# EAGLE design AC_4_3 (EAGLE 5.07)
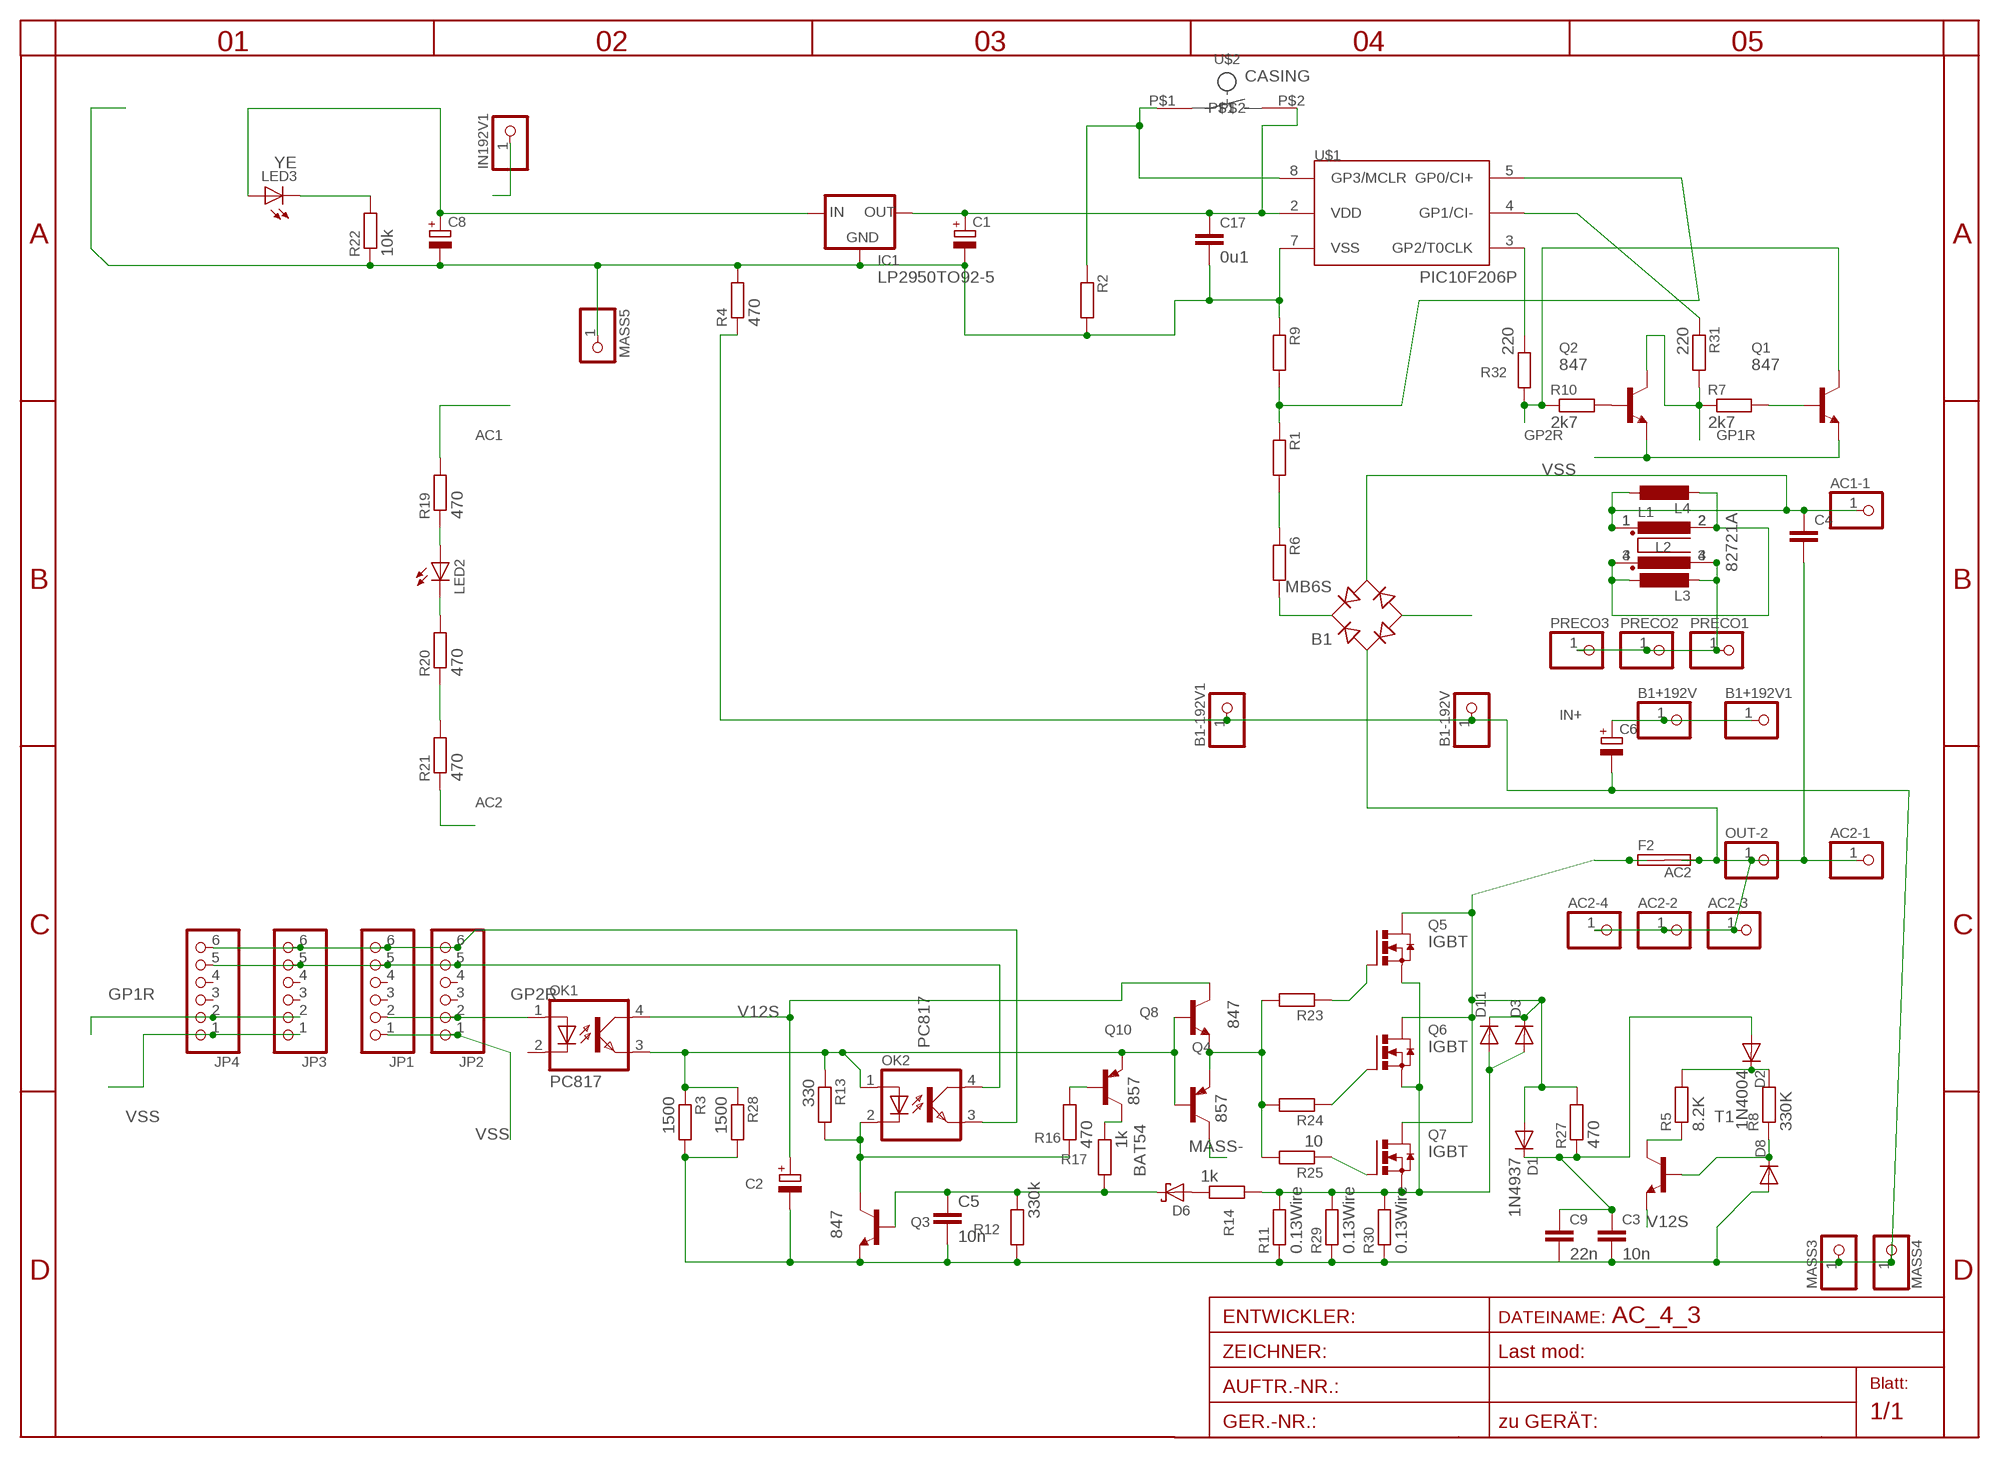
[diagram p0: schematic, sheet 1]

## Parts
AC1-1  PINHD-1X14.5MM  [1X4MM5]
AC2-1  PINHD-1X14.5MM  [1X4MM5]
AC2-2  PINHD-1X13MM2  [1X3MM2]
AC2-3  PINHD-1X13MM2  [1X3MM2]
AC2-4  PINHD-1X12MM3  [1X2MM3]
B1  MB6S  [SOIC-4]
B1+192V  PINHD-1X13MM2  [1X3MM2]
B1+192V1  PINHD-1X13MM2  [1X3MM2]
B1-192V  PINHD-1X13MM2  [1X3MM2]
B1-192V1  PINHD-1X13MM2  [1X3MM2]
C1  CPOL-EUE5-6  [E5-6]
C2  CPOL-EUE2.5-5  [E2,5-5]
C3  10n  C-EU025_050-050X075  [C025_050-050X075]
C4  C-EU225-108X268  [C225-108X268]
C5  10n  C-EUC0805  [C0805]
C6  CPOL-EUE10-20  [EB20D]
C8  CPOL-EUE5-5  [E5-5]
C9  22n  C-EU102-043X133  [C102-043X133]
C17  0u1  C-EUC1206  [C1206]
D1  1N4937  1N4004DO41-10  [DO41-10]
D2  1N4004  [DO41-20]
D3  DIODE-SMC  [SMC]
D6  BAT54  [SOT23]
D8  DIODE-MINIMELF  [MINIMELF]
D11  DIODE-SMC  [SMC]
F2  SHK20L7MM5  [7MM5]
IC1  LP2950TO92-5  [T092-5]
IN192V1  PINHD-1X13MM2  [1X3MM2]
JP1  PINHD-1X6  [1X06BOX]
JP2  PINHD-1X6  [1X06BOX]
JP3  PINHD-1X6  [1X06BOX]
JP4  PINHD-1X6  [1X06BOX]
L1  R1405VB1  [B1]
L2  82721A  [82721A]
L3  L-EU2200-15.24  [2200-15.24]
L4  L-EU2200-15.24  [2200-15.24]
LED2  LED3MM  [LED3MM]
LED3  YE  LEDCHIPLED_1206  [CHIPLED_1206]
MASS3  PINHD-1X13MM2  [1X3MM2]
MASS4  PINHD-1X13MM2  [1X3MM2]
MASS5  PINHD-1X11MM6  [1X1MM8]
OK1  PC817  [DIL04]
OK2  PC817  [DIL04]
OUT-2  PINHD-1X13MM2  [1X3MM2]
PRECO1  PINHD-1X12MM3  [1X2MM3]
PRECO2  PINHD-1X13MM2  [1X3MM2]
PRECO3  PINHD-1X12MM3  [1X2MM3]
Q1  847  BC847ALT1SMD  [SOT23]
Q2  847  BC847ALT1SMD  [SOT23]
Q3  847  BC846ALT1SMD  [SOT23]
Q4  857  BC857ALT1SMD  [SOT23-BEC]
Q5  IGBT  N-HEXFET_DPAK-  [TO252]
Q6  IGBT  N-HEXFET_DPAK-  [TO252]
Q7  IGBT  N-HEXFET_DPAK-  [TO252]
Q8  847  BC846ALT1SMD  [SOT23]
Q10  857  BC857ALT1SMD  [SOT23-BEC]
R1  R-EU_0207/40  [0207/40]
R2  R-EU_R0805  [R0805]
R3  1500  R-EU_R0805  [R0805]
R4  470  R-EU_0204/5  [0204/5]
R5  8.2K  R-EU_0204/5  [0204/5]
R6  R-EU_0207/50  [0207/50]
R7  2k7  R-EU_R0805  [R0805]
R8  330K  R-EU_0204/5  [0204/5]
R9  R-EU_R0805  [R0805]
R10  2k7  R-EU_R0805  [R0805]
R11  0.13Wire  R-EU_0204/5  [0204/5]
R12  330k  R-EU_R0805  [R0805]
R13  330  R-EU_R1206  [R1206]
R14  1k  R-EU_R0805  [R0805]
R16  470  R-EU_R0805  [R0805]
R17  1k  R-EU_R0805  [R0805]
R19  470  R-EU_0204/5  [0204/5]
R20  470  R-EU_0204/2V  [0204V]
R21  470  R-EU_0204/5  [0204/5]
R22  10k  R-EU_R1206  [R1206]
R23  R-EU_0207/15  [0207/15]
R24  R-EU_0207/10  [0207/10]
R25  10  R-EU_0207/15  [0207/15]
R27  470  R-EU_0207/10  [0207/10]
R28  1500  R-EU_R1206  [R1206]
R29  0.13Wire  R-EU_0204/5  [0204/5]
R30  0.13Wire  R-EU_0204/5  [0204/5]
R31  220  R-EU_R1206  [R1206]
R32  220  R-EU_R1206  [R1206]
T1  -NPN-TO92-EBC  [TO92-EBC]
U$1  PIC10F206P  [DIL8]
U$2  CASING  [CASING]

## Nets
AC1: AC1-1.1 B1.~2(AC2) C4.1 L1.1 L2.1 L4.1 R19.2
AC2: AC2-1.1 AC2-2.1 AC2-3.1 AC2-4.1 B1.~1(AC1) C4.2 F2.2A F2.2B OUT-2.1 R21.1
BATT+: C8.+ IC1.3(IN) LED3.A
D1: D1.A D3.C D11.C F2.1A F2.1B Q5.3(D) Q6.3(D) Q7.3(D) R27.2
GP1R: JP3.2 JP4.2 Q2.3(C) R7.1 R31.2
GP2R: JP1.2 JP2.2 OK1.1(A) Q1.3(C) R10.1 R32.2
GP3: JP1.6 JP2.6 JP3.6 JP4.6 OK2.3(EMIT) R2.1 U$1.8(GP3/MCLR) U$2.P$1
IN+: B1+192V1.1 B1+192V.1 C6.+ IN192V1.1
INN: L1.2 L1.3 L2.2 L2.4 L3.1 L4.2
MASS-: B1-192V1.1 B1-192V.1 B1.- C2.- C3.3 C5.2 C6.- C9.2 D8.A MASS3.1 MASS4.1 Q3.2(E) Q4.C R3.2 R4.1 R11.1 R12.2 R28.2 R29.1 R30.1
N$1: R1.1 R9.2 U$1.5(GP0/CI+)
N$2: C3.1 C9.1 D1.C D2.A R27.1
N$3: R1.2 R6.1
N$4: Q2.1(B) R10.2
N$6: LED2.A R19.1
N$7: Q1.1(B) R7.2
N$9: LED2.K(C) R20.2
N$11: C5.1 D6.3(C) Q3.1(B) R12.1 R17.2
N$12: OK2.2(C) Q3.3(C) R13.2 R16.1
N$13: R20.1 R21.2
N$14: D6.1(A) R14.1
N$15: LED3.C R22.2
N$16: Q10.B R16.2
N$17: Q10.C R17.1
N$20: D2.C R5.2 R8.2
N$25: Q7.1(G) R25.1
N$26: Q6.1(G) R24.1
N$27: Q5.1(G) R23.1
N$33: B1.+ R6.2
N$34: R5.1 T1.C
N$36: D8.C R8.1 T1.B
N$37: Q4.E Q8.2(E) R23.2 R24.2 R25.2
N$39: R31.1 U$1.4(GP1/CI-)
N$43: R32.1 U$1.3(GP2/T0CLK)
PP1: OK1.3(EMIT) OK2.1(A) Q4.B Q8.1(B) Q10.E R3.1 R13.1 R28.1
PRECOIL: L1.4 L2.3 L3.2 PRECO1.1 PRECO2.1 PRECO3.1
SRC1: D3.A D11.A Q5.2(S) Q6.2(S) Q7.2(S) R11.2 R14.2 R29.2 R30.2
V12S: C2.+ OK1.4(COL) Q8.3(C) T1.E
VDD: C1.+ C17.1 IC1.1(OUT) JP1.5 JP2.5 JP3.5 JP4.5 OK2.4(COL) U$1.2(VDD) U$2.P$2
VSS: C1.- C8.- C17.2 IC1.2(GND) JP1.1 JP2.1 JP3.1 JP4.1 MASS5.1 Q1.2(E) Q2.2(E) R2.2 R4.2 R9.1 R22.1 U$1.7(VSS)
Unconnected: JP1.3 JP1.4 JP2.3 JP2.4 JP3.3 JP3.4 JP4.3 JP4.4 OK1.2(C)

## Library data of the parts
AC1-1 AC2-1-AC2-4 B1+192V B1+192V1 B1-192V B1-192V1 IN192V1 MASS3-MASS5 OUT-2 PRECO1-PRECO3 = pinhead:PINHD-1X1: PIN HEADER
B1 = rectifier:MB*S: Bridge Rectifier Source: http://www.fairchildsemi.com/ds/MB/MB6S.pdf
C1 C2 C8 = rcl-2:CPOL-EU: POLARIZED CAPACITOR, European symbol
C3 C9 C17 = rcl-2:C-EU: CAPACITOR, European symbol
C4 C5 = rcl:C-EU: CAPACITOR, European symbol
C6 = rcl:CPOL-EU: POLARIZED CAPACITOR, European symbol
D1 D2 = diode:1N4004: DIODE
D3 D8 D11 = diode:DIODE-: DIODE
D6 = diode:BAT54: Schottky Diodes
F2 = fuse:SHK20L: FUSE HOLDER 5 x 20 mm, SH contact, SHH1 Schukat, E1073 Buerklin
IC1 = v-reg:LP2950?*: Source: http://cache.national.com/ds/LP/LP2950.pdf
JP1-JP4 = pinhead:PINHD-1X6: PIN HEADER
L1 = inductor-nkl:R1405V: Übertrager (verlustarm) bis typ. 400kHz Power transformer (low loss) up to typ. 400kHz
L2 = inductors:82721A: FILTER
L3 L4 = rcl:L-EU: INDUCTOR, European symbol
LED2 LED3 = led:LED: LED
OK1 OK2 = optocoupler:PC817: SHARP OPTO COUPLER
Q1 Q2 = transistor-npn:BC847*: NPN Transistor
Q3 Q8 = transistor-npn:BC846*: NPN Transistor
Q4 Q10 = transistor-pnp:BC857*: PNP Transistror
Q5-Q7 = transistor-power:N-HEXFET_?-*: HEXFET® Power MOSFET
R1-R14 R16 R17 R19-R25 R27-R32 = rcl-2:R-EU_: RESISTOR, European symbol
T1 = transistor-neu-to92:*-NPN-: NPN Transistror
U$1 = microchip-5:PIC10F2*: uPC nW 0,25/0,5k Program Flash memory Comparator
U$2 = button:CASING

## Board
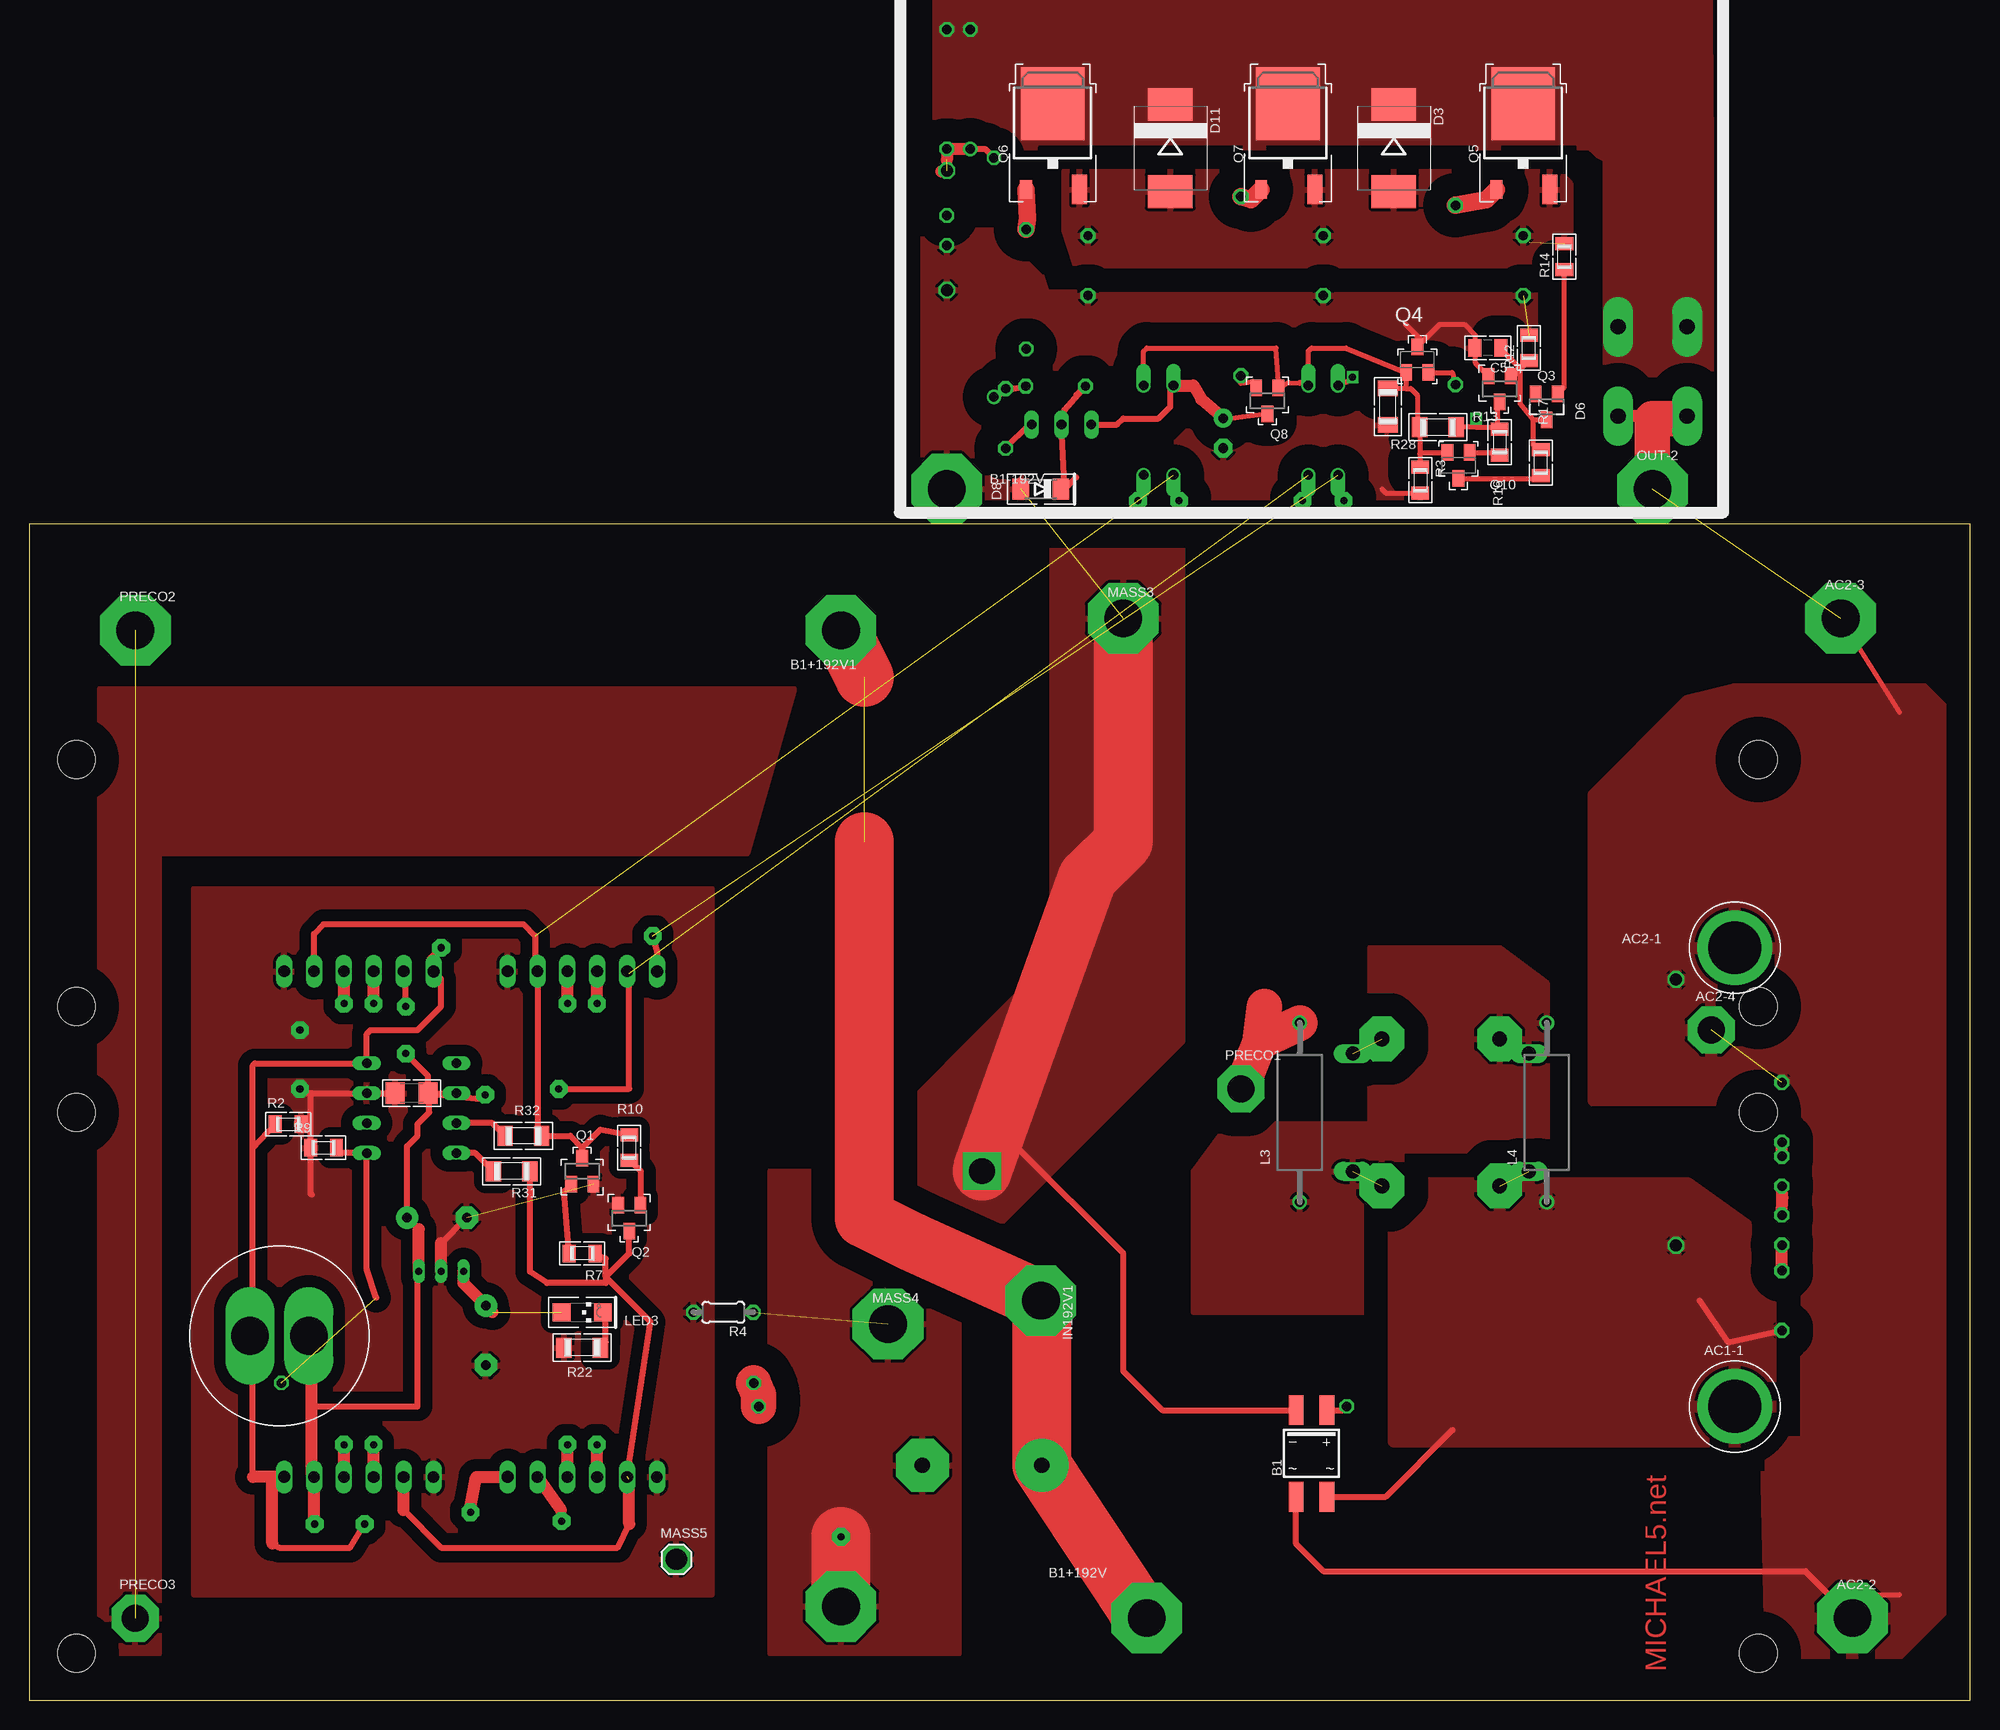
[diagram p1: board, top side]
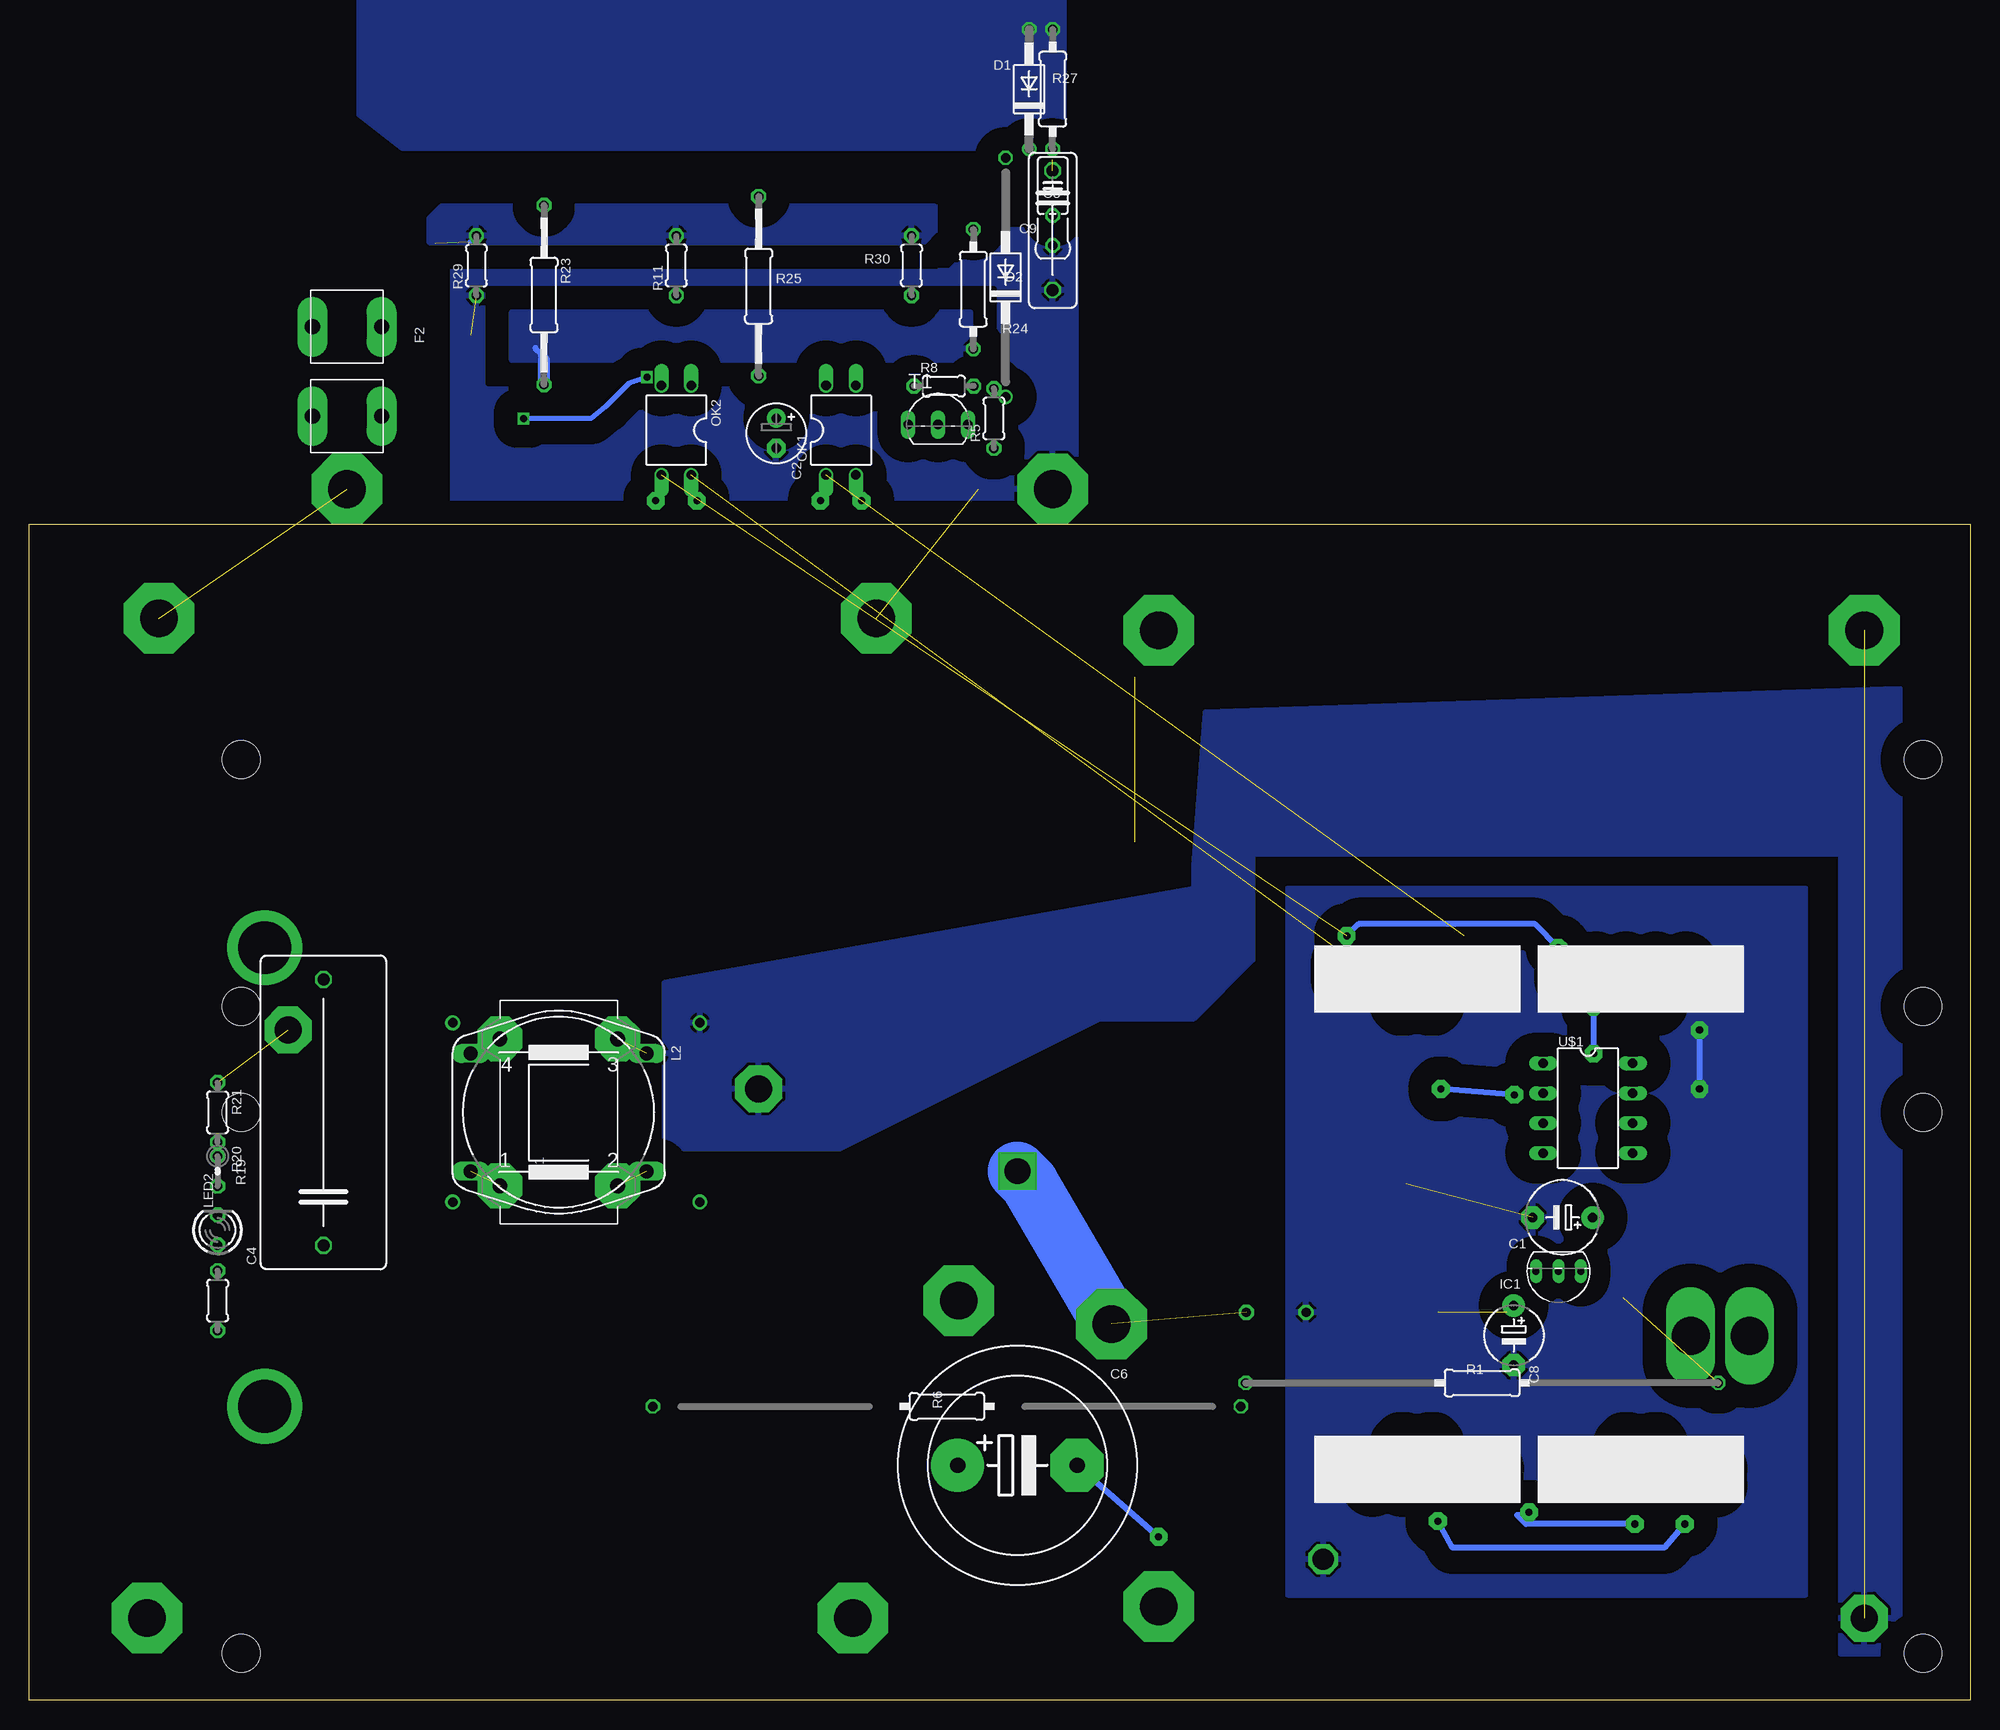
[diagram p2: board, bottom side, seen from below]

Size 165 x 100 mm. Coordinates in mm from the lower left corner, seen from the top.
Outline: 0,0 165,0 165,100 0,100 0,0
Copper layers (1*16): Top 0.035mm / dielectric 1.5mm / Bottom 0.035mm
Design rules "default *": minimum track width 12mil, minimum drill 24mil, track to track 8mil, track to pad 8mil, pad to pad 8mil, via to via 8mil, smd to smd 8mil, copper to edge 40mil, drill to drill 8mil, minimum pad ring 8mil, minimum via ring 8mil, stop-mask expansion 4mil, vias tented up to drill 0mil, thermal gap 10mil
Holes 3.2 mm at 4,80 4,4 4,59 4,50 147,80 147,4 147,59 147,50

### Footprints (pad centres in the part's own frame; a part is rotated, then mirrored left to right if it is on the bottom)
1X4MM5 = drill 4.5 pad 6.35 round: 1 0,0
1X3MM2 = drill 3.2 pad 6 octagon: 1 0,0
1X2MM3 = drill 2.3 pad 4 octagon: 1 0,0
SOIC-4 = smd 1.27 x 2.54: + 1.3,3.685; - -1.3,3.685; ~1 -1.3,-3.685; ~2 1.3,-3.685
E5-6 = drill 0.813 pad 1.905 round: + -2.54,0 | drill 0.813 pad 1.905 octagon: - 2.54,0
E2,5-5 = drill 0.813 pad 1.6 round: + -1.27,0 | drill 0.813 pad 1.6 octagon: - 1.27,0
C025_050-050X075 = drill 0.813 octagon: 1 -3.81,0; 2 0,0; 3 2.54,0
C225-108X268 = drill 1.016 octagon: 1 -11.303,0; 2 11.303,0
C0805 = smd 1.1 x 1.5: 1 -1.1,0; 2 1.1,0
EB20D = drill 1.3 pad 4.5 round: + -5.08,0 | drill 1.3 pad 4.5 octagon: - 5.08,0
E5-5 = drill 0.813 pad 1.905 round: + -2.54,0 | drill 0.813 pad 1.905 octagon: - 2.54,0
C102-043X133 = drill 1.016 octagon: 1 -5.08,0; 2 5.08,0
C1206 = smd 1.6 x 1.8: 1 -1.4,0; 2 1.4,0
DO41-10 = drill 0.8 octagon: A 5.08,0 | drill 0.8 round: C -5.08,0
DO41-20 = drill 0.8 octagon: A 10.16,0 | drill 0.8 round: C -10.16,0
SMC = smd 2.8 x 3.8: A 3.7,0; C -3.7,0
SOT23 = smd 1 x 1.4: 1 -0.95,-1.1; 2 0.95,-1.1; 3 0,1.1
MINIMELF = smd 1.4 x 1.8: A 1.7,0; C -1.7,0
7MM5 = drill 1.3 pad 2.54 long: 1A -3.8,2.94; 1B -3.8,-2.94; 2A 3.8,2.94; 2B 3.8,-2.94
T092-5 = drill 0.6 pad 0.813 long: 1 -1.905,0; 2 0,0; 3 1.905,0
1X06BOX = drill 1 long: 1 -6.35,0; 2 -3.81,0; 3 -1.27,0; 4 1.27,0; 5 3.81,0 | drill 1.016 long: 6 6.35,0
B1 = drill 1.27 pad 3.81 octagon: 1 -6.25,5; 2 -6.25,-5; 3 6.25,5; 4 6.25,-5
82721A = drill 1.194 long: 1 7.493,5.004; 2 -7.493,5.004; 3 -7.493,-5.004; 4 7.493,-5.004
2200-15.24 = drill 0.8 pad 1.27 round: 1 -7.62,0; 2 7.62,0
LED3MM = drill 0.8 pad 1.27 octagon: A -1.27,0; K 1.27,0
CHIPLED_1206 = smd 1.5 x 1.5: A 0,-1.75; C 0,1.75
1X1MM8 = drill 1.8 pad 2.54 octagon: 1 0,0
DIL04 = drill 0.813 offset: 1 -1.27,-3.81; 2 1.27,-3.81; 3 1.27,3.81; 4 -1.27,3.81
SOT23-BEC = smd 1 x 1.4: B -0.95,-1.1; C 0,1.1; E 0.95,-1.1
TO252 = smd 1 x 1.6: 1 -2.28,-3.53 | smd 1.27 x 2.54: 2 2.28,-3.53 | smd 5.4 x 6.2: 3 0,3.77
0207/40 = drill 0.813 octagon: 1 -20.08,0; 2 20.08,0
R0805 = smd 1.1 x 1.5: 1 -1.1,0; 2 1.1,0
0204/5 = drill 0.8 pad 1.27 octagon: 1 -2.54,0; 2 2.54,0
0207/50 = drill 0.813 octagon: 1 -25,0; 2 25,0
R1206 = smd 1.3 x 1.7: 1 -1.55,0; 2 1.55,0
0204V = drill 0.8 pad 1.27 octagon: 1 -1.27,0; 2 1.27,0
0207/15 = drill 0.8 pad 1.27 octagon: 1 -7.62,0; 2 7.62,0
0207/10 = drill 0.813 octagon: 1 -5.08,0; 2 5.08,0
TO92-EBC = drill 0.813 long: B 0,-1.27; C 2.54,-1.27; E -2.54,-1.27
DIL8 = drill 0.8 long: 1 -3.81,-3.81; 2 -1.27,-3.81; 3 1.27,-3.81; 4 3.81,-3.81; 5 3.81,3.81; 6 1.27,3.81; 7 -1.27,3.81; 8 -3.81,3.81
CASING = drill 3.2 pad 3.81 long: P$1 -2.5,0; P$2 2.5,0

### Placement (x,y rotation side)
AC1-1  145,25 0 top
AC2-1  145,64 0 top
AC2-2  155,7 0 top
AC2-3  154,92 0 top
AC2-4  143,57 0 top
B1  109,21 0 top
B1+192V  95,7 0 top
B1+192V1  69,91 180 top
B1-192V  78,103 0 top
B1-192V1  69,8 0 top
C1  34.65,41.07 180 bottom
C2  101.5,107.75 270 bottom  (outside the outline)
C3  not placed on the board
C4  140,50 90 bottom
C5  124,115 180 top  (outside the outline)
C6  81,20 0 bottom
C8  38.8,31.05 270 bottom
C9  78,125 270 bottom  (outside the outline)
C17  32.49,51.63 180 top
D1  80,137 90 bottom  (outside the outline)
D2  82,121 90 bottom  (outside the outline)
D3  not placed on the board
D6  129,110 180 top  (outside the outline)
D8  86,103 180 top
D11  not placed on the board
F2  138,113 270 bottom  (outside the outline)
IC1  35,36.5 180 bottom
IN192V1  86,34 270 top
JP1  47,62 180 bottom
JP2  28,62 180 bottom
JP3  28,19 0 bottom
JP4  47,19 0 bottom
L1  120,50 90 bottom
L2  120,50 180 bottom
L3  108,50 90 top
L4  129,50 90 top
LED2  149,40 90 bottom
LED3  47,33 270 top
MASS3  93,92 0 top
MASS4  73,32 0 top
MASS5  55,12 0 top
OK1  96,108 0 bottom  (outside the outline)
OK2  110,108 180 bottom  (outside the outline)
OUT-2  138,103 0 top
PRECO1  103,52 0 top
PRECO2  9,91 0 top
PRECO3  9,7 0 top
Q1  47,45 0 top
Q2  51,41 180 top
Q3  125,111.5 180 top  (outside the outline)
Q4  118,114 0 top  (outside the outline)
Q5  127,132 0 top  (outside the outline)
Q6  87,132 0 top  (outside the outline)
Q7  107,132 0 top  (outside the outline)
Q8  105.25,110.5 180 top  (outside the outline)
Q10  121.5,105 180 top  (outside the outline)
R1  41.5,27 180 bottom
R2  22,49 0 top
R3  118.25,103.75 270 top
R4  59,33 180 top
R5  83,109 90 bottom  (outside the outline)
R6  87,25 180 bottom
R7  47,38 180 top
R8  87.25,111.75 0 bottom  (outside the outline)
R9  25,47 0 top
R10  51,47 270 top
R11  not placed on the board
R12  127.5,115 90 top  (outside the outline)
R13  119.75,108.25 0 top  (outside the outline)
R14  130.5,122.75 90 top  (outside the outline)
R16  125,107 270 top  (outside the outline)
R17  128.5,105.25 90 top  (outside the outline)
R19  149,34 270 bottom
R20  149,45 270 bottom
R21  149,50 270 bottom
R22  47,30 0 top
R23  121.25,119.5 270 bottom  (outside the outline)
R24  84.75,120 270 bottom  (outside the outline)
R25  103,120.25 270 bottom  (outside the outline)
R27  78,137 90 bottom  (outside the outline)
R28  115.5,110 270 top  (outside the outline)
R29  127,122 90 bottom  (outside the outline)
R30  not placed on the board
R31  41,45 0 top
R32  42,48 0 top
T1  87.75,109.75 0 bottom  (outside the outline)
U$1  32.49,50.36 270 bottom
U$2  21.25,31 0 top

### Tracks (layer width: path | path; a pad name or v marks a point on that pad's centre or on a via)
AC1  (1 unrouted)
  Top 0.5: R19.2 144.46,30.46 142,34 | B1.~2 115.31,17.32 121,23
  pour Top (isolate 2): 116,44 141,44 148,39 148,22 116,22
AC2  (2 unrouted)
  Top 0.406: 159,84 AC2-3.1 | 159,9 155,9 AC2-2.1
  Top 0.5: B1.~1 107.7,13.3 110,11 151,11 AC2-2.1
  Top 1: F2.2A F2.2B 140.74,109 140,109
  Top 3: OUT-2.1 138,109 140,109
  pour Top (isolate 2, rank 2): 145,86 161,86 163,84 163,8 159,4 149,4 148,5 147,51 133,51 133,77 141,85
BATT+  (1 unrouted)
  Top 1: IC1.3 36.91,35.48 C8.+ 39.38,33
D1
  pour Top (isolate 2, rank 2, no thermals): 77,148 142.89,148 143,132 143,111 134,111 134,131 132,132 77,132
  pour Bottom (isolate 2, rank 2, no thermals): 77,148 137,148 137,134.82 133.35,132 77,132
GP1R  (1 unrouted)
  Top 0.5: R31.2 42.55,36.45 44,35.5 49,35.5 49,36 | 49,36 49,37.55 R7.1 | Q2.3 51,38 49,36 | 49,36 52.81,32.19 JP4.2 | 31.81,16.19 35,13 50,13 51,15
  Top 1: 51,15 51,18.81 | 31.81,16.19 JP3.2
GP2R  (1 unrouted)
  Top 0.5: R10.1 48.55,48.55 47,47 | 47,47 Q1.3 | 47,47 46,48 R32.2 43.19,48.36 JP1.2 43,62.19 43,65 42,66 25,66 24.19,65.19 JP2.2
GP3  (via drill 0.6 pad 1.5)  (1 unrouted)
  Top 0.5: 20.65,13.35 21.25,13 27.25,13 v28.5,15 | 19,19 19,27.5 U$2.P$1 19,32.5 19,47 | 19,47 R2.1 | 19,47 19,54 19.17,54.17 U$1.8 28.68,56.68 29,57 33,57 35,59 35,61.35 JP2.6 34,62.35 34,63 v35,64 | 20.65,18.65 21,19 | v37.5,16 37.5,16.5 | JP1.6 53.35,63.65 v53,65
  Top 1: 19,19 JP3.6 21,19 | 20.65,13.35 20.65,18.65 | 37.5,16.5 38,19 JP4.6
  Bottom 0.5: v28.5,15 37.75,15 38.5,15.75 v37.5,16 | v53,65 52,66 37,66 v35,64
IN+  (1 unrouted)
  Top 5: B1+192V.1 94.08,7.92 C6.+ 86.08,31.92 IN192V1.1 75,39 71,41 71,73 | 71,87 B1+192V1.1
INN  (1 unrouted)
  pour Top (isolate 2, rank 2): 114,64 125,64 129,61 129,46 114,46 114,33 99,33 99,45 102,49 114,49
MASS-  (via drill 0.6 pad 1.5, 2.2 pad 3)  (3 unrouted)
  Top 0.406: R3.2 115.35,102.65 115,103 | 118.3,115.7 117,117 | Q3.2 122.9,113.75 C5.2 122.9,116.1 122,117 119.9,117 Q4.C
  Top 0.5: B1.- 96.31,24.68 93,28 93,38 84,47
  Top 5: B1-192V1.1 v69,13.92 | MASS3.1 93,73 90,70 v81,45
  Bottom 0.5: v69,13.92 C6.-
  Bottom 5: MASS4.1 80,44 v81,45
  pour Top (isolate 2, rank 3): 76,125 82,125 86,121 129,121 129,102 76,102
  pour Bottom (isolate 2, rank 3): 76,125 82,125 86,122 129,122 129,102 76,102
  pour Top (isolate 2, rank 3): 87,99 98,98 98,56 79,37 79,4 63,4 63,45 69,45 87,63
N$1  (1 unrouted)
  Top 0.5: 29.5,34.25 28.68,36.68 U$1.5 26.55,46.55 R9.2
N$2  (2 unrouted)
  Top 0.5: D1.C 81.24,131.92 D2.A
  Top 1: D1.C R27.1 78,131 | C9.1 77.54,130
N$3
  Top 3: R6.1 62,26 R1.2
N$4
  Top 0.5: R10.2 51.55,45.45 52,45 52,42.15 Q2.1
N$5  (via drill 0.6 pad 1.5)
  Top 1: 48.25,19 v48.25,21.75
N$6
  Top 1.016: R19.1 LED2.A
N$7
  Top 0.5: R7.2 45.45,43.3 Q1.1
N$8  (via drill 0.6 pad 1.5)
  other vias: 45.75,21.75
N$9
  Top 1.016: R20.2 149.04,42.73 LED2.K
N$10  (via drill 0.6 pad 1.5)
  other vias: 26.75,21.75
N$11
  Top 0.406: 127.85,108.9 D6.3 | 127.85,108.9 126.75,110.25 126.75,113.25 | 126.75,113.25 127,113.4 R12.1 126.2,112.6 Q3.1 | 127.85,108.9 127.85,106.75 R17.2 | C5.1 125.1,114.9 126.75,113.25
N$12  (via drill 0.6)
  Top 0.406: 123,108.25 R13.2 | 123,108.25 124.85,108.25 | 124.85,108.25 R16.1 | 124.85,108.25 124.85,110.25 Q3.3 | OK2.2 112.31,112.31 v112.5,112.5 | v123,109 123,108.25
  Bottom 0.406: v112.5,112.5 114,112 116,110 117.25,109 v123,109
N$13
  Top 1.016: R20.1 R21.2
N$14
  Top 0.406: R14.1 130.5,111.65 D6.1
N$15
  Top 0.5: LED3.C 49,33 49,30.45 R22.2
N$16
  Top 0.406: Q10.B 124.8,106.1 R16.2
N$17
  Top 0.406: Q10.C 128.25,103.9 R17.1
N$18  (via drill 0.6 pad 1.5)
  Top 1: 29.25,19 v29.25,21.75
N$19  (via drill 0.6 pad 1.5)
  Top 1: v48.25,59.25 48.25,62
N$20
  Top 0.5: D2.C 82.3,110.84 R5.2 83.67,111.54 R8.2
N$21  (via drill 0.6 pad 1.5)
  other vias: 111.75,102
N$22  (via drill 0.6 pad 1.5)
  other vias: 108.25,102
N$23  (via drill 0.6 pad 1.5)
  other vias: 97.75,102
N$24  (via drill 0.6 pad 1.5)
  other vias: 94.25,102
N$25
  Top 1.5: R25.1 103.87,127.62 Q7.1
N$26
  Top 1.5: Q6.1 84.85,125.97 R24.1
N$27
  Top 1.5: R23.1 123.87,127.62 Q5.1
N$28  (via drill 0.6 pad 1.5)
  Top 1: v45.75,59.25 45.75,62
N$29  (via drill 0.6 pad 1.5)
  Top 1: v29.25,59.25 29.25,62
N$30  (via drill 0.6 pad 1.5)
  Top 1: v26.75,59.25 26.75,62
N$31
  Top 1: 45.75,19 45.75,21.5
N$32
  Top 1: 26.75,19 26.75,21.5
N$33
  Top 0.5: B1.+ 111.69,24.68 R6.2
N$34
  Top 0.5: T1.C 85.02,108.48 R5.1
N$36
  Top 0.5: 89,111 R8.1 88,109.71 T1.B 88,103.3 D8.C 88,103 89,104
N$37
  Top 0.406: R25.2 103,112 104,112.15 Q8.2 | Q4.E 120.98,112.9 R23.2
  Bottom 0.406: R25.2 103,116
  Bottom 0.5: R23.2 121.5,114.5 122,115
  Bottom 1: R23.2 121.25,114
  pour Bottom (isolate 2, rank 2): 85,118 124,118 124,114 85,114
N$39
  Top 0.5: U$1.4 37.9,46.55 R31.1
N$43
  Top 0.5: U$1.3 39.36,49.09 R32.1
PP1
  Top 0.406: OK1.3 94.73,114.73 95,115 106,115 105.95,114.95 Q8.1 107.05,112.05 108,112 108,112.08 OK2.1 108.73,114.73 109,115 111.95,115 Q4.B 117.05,111.6 117,111.55 | 117,111.55 117.45,111.55 118,111 118,108.45 R13.1 118.2,106 | 117,111.55 R28.1 | 118.2,106 118.2,104.9 R3.1 | Q10.E 118.3,106.1 118.2,106
PRECOIL  (2 unrouted)
  Top 3: PRECO1.1 104.62,56 | 104.62,56 105,59 | 104.62,56 L3.2
  pour Bottom (isolate 2): 6,86 65,84 66,71 66,69 111,61 111,47 96,47 74,58 66,58 61,63 61,72 11,72 11,4 6,4
  pour Top (isolate 2): 6,86 65,86 61,72 11,72 11,4 6,4
SRC1  (1 unrouted)
  Bottom 0.406: 127.54,124 R29.2
  pour Top (isolate 2): 88,130 130,130 131,129 131,124 130,122 89,122 88,125
  pour Bottom (isolate 2): 88,127 130,127 131,126 131,124 89,124 88,125
V12S
  Top 0.406: Q8.3 103.1,109.15 102,109 101.52,109 C2.+
  Top 0.5: T1.E 92.48,108.48 93,109 96,109 97,110 97,111.54 OK1.4
  Top 1: C2.+ 99.64,110.64 98.96,111.81 OK1.4
VDD  (via drill 0.6 pad 1.5)  (1 unrouted)
  Top 0.5: 33.09,40.09 C1.+ 32.11,47.11 33,48 33,49 34,50 34,51.52 C17.1 | C17.1 U$1.2 | 24,25 33,25 33,36 33.09,36.09 IC1.1 | v45.25,15.25 45.19,16.19 | 24,28.75 U$2.P$2 | C17.1 38.38,51.13 v38.75,51.5 | v45,52 51,52 51,61.81 JP1.5 | C17.1 33.89,53.11 v32,55 | v32,59 32,61.81 JP2.5 | JP3.5 24,19.19 | v24.25,15 24.19,15.31
  Top 1: IC1.1 33.09,40.09 | 24,28.75 24,25 24,19.19 | 45.19,16.19 JP4.5 | 24.19,15.31 JP3.5
  Bottom 0.5: v45.25,15.25 44,13 26,13 v24.25,15 | v38.75,51.5 v45,52 | v32,55 v32,59
VSS  (via drill 0.6 pad 1.5)  (1 unrouted)
  Top 0.5: U$1.7 28.68,52 | 24,51.63 23.37,51.63 v23,52 | 24,51.63 U$1.7 | 23.9,49 R9.1 23.9,43.1 24,43 | 23.9,49 23.9,51.53 24,51.63 | 35,38.88 C1.- | U$1.7 C17.2 | 23.9,49 R2.2
  Top 1: IC1.2 35,38.88
  Bottom 0.5: v23,52 v23,57
  pour Bottom (isolate 2): 14,69 58,69 58,9 14,9
  pour Top (isolate 1): 14,69 58,69 58,9 14,9

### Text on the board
Top: MICHAEL5.net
